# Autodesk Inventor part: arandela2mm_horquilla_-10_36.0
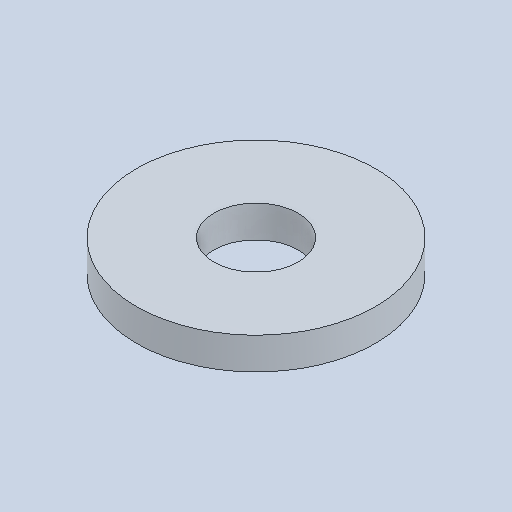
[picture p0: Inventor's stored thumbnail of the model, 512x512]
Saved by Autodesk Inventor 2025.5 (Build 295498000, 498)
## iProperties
Created: 2026-10
Part Number: arandela2mm_horquilla_-10_36.0
Material: Genérico
Document SubType Name: Modeling
Designer: Luis M
Density: 1 g/cm^3
Appearance: Valor por defecto
Author: Luis M
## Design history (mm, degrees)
feature "Base1"
node "Sólido1"
